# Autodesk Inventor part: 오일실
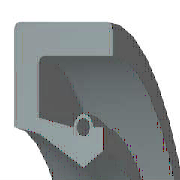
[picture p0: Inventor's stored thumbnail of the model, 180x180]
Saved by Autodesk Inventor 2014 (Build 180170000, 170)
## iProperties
Company: 한국ATC센터
IsCustomPart: 1
Created: 2009-02
Part Number: 오일실
Material: 고무
Description: 오일-실
Document SubType Name: Modeling
Standard: KS B 2804
Designer: KYOUNG IL JANG
Standards Organization: KS
Language: ko-KR
Size Designation: S - 12 22 7
Categories: <MemberInstance><Categories><Category DisplayName="샤프트 부품" InternalName="7f7aeb1f-a693-4053-b835-cee3144e0d98" Mnemonic="SHFT"><Category DisplayName="실링" Intern
Density: 0.93 g/cm^3
Mass: 1.0258 g
Surface Area: 17.5559 cm^2
Volume: 1.10301 cm^3
Vendor: CBT Solutions
Appearance: 고무 - 검은색 - 버전 1.1
Author: KYOUNG IL JANG
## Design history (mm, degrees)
revolve "본체" stored, may be unused: angle "d17" = 90 deg
revolve "스프링1" stored, may be unused: angle "d18" = 90 deg
body "Solid1"
sketch "스케치1"
  geometry: L1 (0, 11)-(7, 11); L2 (7, 11)-(7, 9.75); L3 (7, 9.75)-(1.75, 9.75); L4 (0, 11)-(0, 8.1); L5 (0, 8.1)-(1.75, 7.75); L6 (1.75, 7.75)-(4.9, 6); L7 (4.9, 6)-(0, 6); L8 (6.3, 6.875)-(6.3, 8.1); L9 (0, 0)-(9.586, 0) reference; L10 (4.9, 6)-(6.3, 6.875); L11 (0, 18)-(0, -3) reference; L12 (-1.917, 0)-(11.503, 0) reference; L13 (4.2, 8.1)-(1.75, 8.59); L14 (1.75, 8.59)-(1.75, 9.75); L15 (6.3, 8.1)-(5.6, 8.1); C1 r 0.455 at (4.9, 8.1); A1 r 0.7 centre (4.9, 8.1) between (5.6, 8.1) and (4.2, 8.1)
  constraints: 26 end point, 5 horizontal alignment, 4 perpendicular, 2 centre point, 2 collinear, 2 horizontal, 2 parallel, 2 point on circle, 2 point on line, 2 vertical alignment, 1 coincident
  dimensions: "d0" = 22 diameter of L1 L9 (= SD2); "d1" = 13.75 diameter of L8.start L9 (= ABDM); "d2" = 1.25 distance of L1.end L2.end (computed from SD); "d3" = 0.91 diameter of C1 (= SPDI); "d4" = 1.4 diameter of A1 (= SPDA); "d5" = 12 diameter of L6.end L9 (= NND); "d6" = 15.5 diameter of L5.end L9 (= TKDM); "d7" = 16.2 diameter of L4.end L9 (= HLDM); "d8" = 4.9 distance from line of C1.centre L4 (= SPDST); "d9" = 6.3 distance between parallel lines of L8 L4 (= SDI); "d10" = 7 distance between parallel lines of L2 L4 (= SWDT); "d12" = 1.75 distance between parallel lines of L14 L4 (= SD)
fillet "모깎기1" dims "d11" = 0.3 (= RR)
other parameters: "SD2" = 22 [user parameter; used in 1 equation term], "SWDT" = 7 [user parameter; used in 1 equation term], "RR" = 0.3 [user parameter; used in 1 equation term], "SD" = 1.75 [user parameter; used in 2 equation terms], "NND" = 12 [user parameter; used in 1 equation term], "SPDA" = 1.4 [user parameter; used in 1 equation term], "SPDI" = 0.91 [user parameter; used in 1 equation term], "TKDM" = 15.5 [user parameter; used in 1 equation term], "HLDM" = 16.2 [user parameter; used in 1 equation term], "ABDM" = 13.75 [user parameter; used in 1 equation term], "SDI" = 6.3 [user parameter; used in 1 equation term], "SPDST" = 4.9 [user parameter; used in 1 equation term], "d13" = 0, "d14" = 0, "d15" = 0, "LAB" = 0.35 [user parameter]
